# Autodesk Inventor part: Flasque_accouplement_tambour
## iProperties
Shininess: 64.0
Length Units: 11269
Angle Units: 11279
Time Units: 11290
Mass Units: 11283
Length Display Precision: 3
Angle Display Precision: 2
Compacted: True
Part Number: Flasque_accouplement_tambour
Document SubType Name: Modeling
Created: 2008-02
Material: Acier inoxydable, austénitique
Designer: Pascal
Density: 0.0
Volumn: 0.0
Area: 0.0
PropertySet Name: Model Information
Control State: 0
Master: False
Checked Out: False
DESIGNATION: pièce
Author: Pascal
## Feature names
1. Extrusion1
2. Extrusion2
3. Chanfrein1 [Chamfer]
4. Extrusion3
